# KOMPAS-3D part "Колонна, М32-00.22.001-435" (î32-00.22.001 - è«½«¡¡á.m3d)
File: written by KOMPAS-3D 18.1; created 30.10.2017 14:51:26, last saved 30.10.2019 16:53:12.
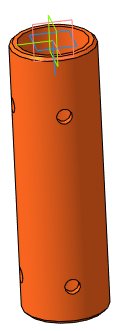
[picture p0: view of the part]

Document properties: Автор: Милов; Организация: Милов; Полное имя файла: D:\Magna\Магна Ins\Магна ins 32\М32-00.22.001 - Колонна.m3d

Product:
- Part/product: Колонна  | designation М32-00.22.001-435
    Масса: 1.21663
- Part/product: Колонна  | designation М32-00.22.001
    Масса: 1.0611
    Раздел спецификации: Детали
    Форматы листов документа: A3
    source file: М32-00.22.001 - Колонна.cdw
- Part/product: Колонна  | designation М32-00.22.001
    Масса: 0.990487
- Part/product: Колонна  | designation М40-10.22.001-ПВХ
    Масса: 0.677738
    source file: ..\Магна ins 40\Магна Ins 40-L-3-N-ПВХ\М40-10.22.001 - Колонна.cdw, М32-00.22.001 - Колонна.cdw

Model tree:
1. Эскиз:1
2. Операция выдавливания:1
     Расстояние 1 = 360
3. Эскиз:2  (with: Операция выдавливания:1)
4. Вырезать элемент выдавливания:1
     Расстояние 1 = 55
5. Массив по концентрической сетке:1  (with: Вырезать элемент выдавливания:1, Эскиз:2)  (4 pattern instances)
     Шаг 2 = 360
6. Фаска:1  (with: Операция выдавливания:1)
     Угол = 45; Длина 1 = 4; Длина 2 = 4

Expressions: 110-6.6*2

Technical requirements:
  Gost Type A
